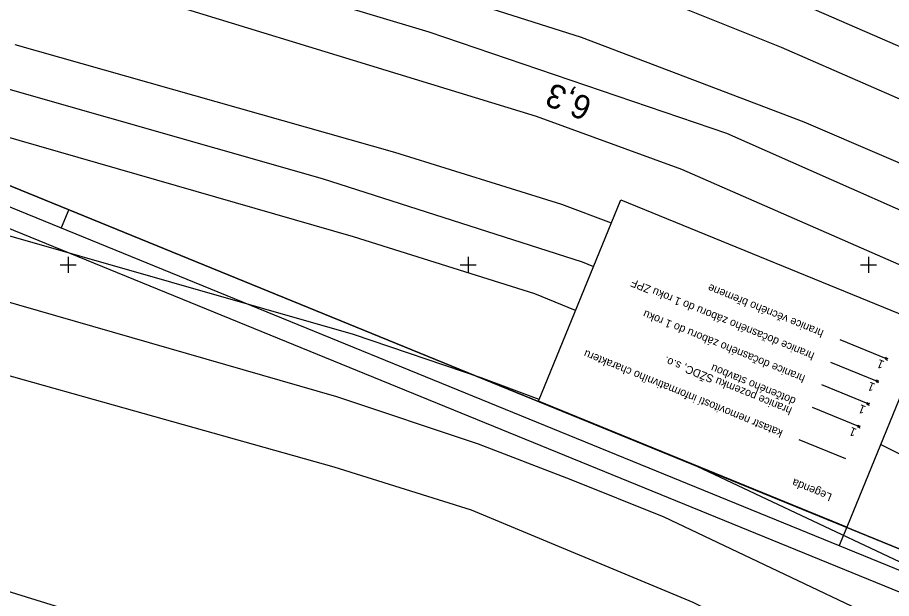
# Model space of a CAD drawing. Extents: x -779302 to -774398, y -1144902 to -1142831.
# Drawn here: x -776612.7 to -776394.2, y -1144283.5 to -1144138.1 of the extents above; entities that cross this region are included whole.
import ezdxf

# ---------------------------------------------------------------- set-up
doc = ezdxf.new("R2010")
doc.units = 0
for name, color, linetype in [('hektosit - Vrstva 5', 7, 'Continuous'), ('Hranice parcel', 7, 'Continuous'), ('legenda - Vrstva 7', 7, 'Continuous'), ('legenda I_5_2 - Vrstva 3', 7, 'Continuous'), ('Vrstva 1', 7, 'Continuous'), ('zjednodus_g_situ-seda - Vrstva 7', 7, 'Continuous')]:
    doc.layers.add(name, color=color, linetype=linetype)

msp = doc.modelspace()

# ---------------------------------------------------------------- linework, layer by layer
at = {"layer": 'hektosit - Vrstva 5'}
for p, q in [((-776600, -1144198), (-776600, -1144202)), ((-776500, -1144198), (-776500, -1144202)), ((-776400, -1144198), (-776400, -1144202)), ((-776602, -1144200), (-776598, -1144200)), ((-776502, -1144200), (-776498, -1144200)), ((-776402, -1144200), (-776398, -1144200))]:
    msp.add_line(p, q, dxfattribs=at)
at = {"layer": 'Hranice parcel'}
for points in [[(-776609.22, -1144072.59), (-776549.62, -1144089.18), (-776477.02, -1144111.9), (-776421.35, -1144132.65), (-776283.48, -1144192.64), (-776246.29, -1144206.67), (-776201.94, -1144223.07), (-776173.05, -1144232.7), (-776113.8, -1144251.1)], [(-776118.46, -1144262.59), (-776213.85, -1144232.45), (-776276.83, -1144209.03), (-776421.73, -1144145.66), (-776463.81, -1144128.69), (-776555.71, -1144099.28), (-776609.79, -1144083.15)], [(-776610.76, -1144099.41), (-776538.78, -1144121.66), (-776471.83, -1144143.05), (-776416.15, -1144164.19), (-776357.31, -1144189.49), (-776292.36, -1144218.98), (-776247.15, -1144237), (-776206.49, -1144251.17), (-776124.24, -1144276.84)], [(-776611.4, -1144111.19), (-776509.83, -1144141.71), (-776435.48, -1144167.03), (-776362.11, -1144199.54), (-776309.74, -1144224.06), (-776263.02, -1144242.23), (-776193.31, -1144267.08), (-776128.39, -1144287.08)], [(-776132.3, -1144298.01), (-776193.18, -1144278.57), (-776239.59, -1144263.48), (-776301.12, -1144240.48), (-776347.51, -1144219.6), (-776446.62, -1144176.16), (-776482.94, -1144162.91), (-776612.01, -1144123.26)], [(-776613.35, -1144144.87), (-776518.43, -1144171.83), (-776476.72, -1144184.79), (-776464.26, -1144189.51)], [(-776616.25, -1144155.62), (-776536.52, -1144178.37), (-776471.51, -1144199.25), (-776468.72, -1144200.44)], [(-776473.19, -1144211.37), (-776483.35, -1144207.28), (-776528.7, -1144193.02), (-776617.26, -1144167.5)], [(-776482.3, -1144233.64), (-776496.78, -1144228.23), (-776528.65, -1144217.4), (-776619.56, -1144191.38)], [(-776145.67, -1144379.15), (-776244.27, -1144349.66), (-776296.05, -1144332.67), (-776327.31, -1144320.71), (-776369.01, -1144302.14), (-776451.08, -1144263.13), (-776474.26, -1144253.76), (-776497.45, -1144244.88), (-776532.83, -1144233.01), (-776621.67, -1144207.38)], [(-776148.27, -1144396.56), (-776184.13, -1144386.14), (-776245.97, -1144366.65), (-776333.82, -1144336.34), (-776380.08, -1144316.22), (-776443.83, -1144284.45), (-776499.21, -1144261.37), (-776533.49, -1144250.6), (-776623.75, -1144225.26)], [(-776139.95, -1144340.89), (-776219.46, -1144316.38), (-776263.77, -1144302.5), (-776324.6, -1144278.51), (-776377.44, -1144254.65), (-776396.98, -1144244.94)], [(-776143.31, -1144363.37), (-776191.33, -1144349.34), (-776249.99, -1144330.39), (-776319.63, -1144305.99), (-776364.66, -1144287.25), (-776444.24, -1144249.74)], [(-776631.25, -1144276.64), (-776433.42, -1144338.06), (-776306.29, -1144376.93), (-776251.08, -1144392.3), (-776152.53, -1144423.14)]]:
    msp.add_lwpolyline(points, dxfattribs=at)
at = {"layer": 'legenda - Vrstva 7'}
msp.add_lwpolyline([(-776405.43, -1144265.6), (-776482.49, -1144234.1), (-776461.9, -1144183.75), (-776384.84, -1144215.25)], close=True, dxfattribs=at)
at = {"layer": 'legenda I_5_2 - Vrstva 3'}
for p, q in [((-776395.45, -1144223.48), (-776407.07, -1144218.74)), ((-776397.76, -1144229.14), (-776409.38, -1144224.39)), ((-776395.19, -1144223.38), (-776395.84, -1144223.65)), ((-776395.71, -1144223.59), (-776395.06, -1144223.32)), ((-776395.34, -1144223.75), (-776395.62, -1144223.09)), ((-776395.56, -1144223.22), (-776395.29, -1144223.88)), ((-776395.45, -1144223.48), (-776395.45, -1144223.48)), ((-776397.65, -1144229.4), (-776397.93, -1144228.74)), ((-776400.07, -1144234.79), (-776411.69, -1144230.04)), ((-776397.5, -1144229.03), (-776398.15, -1144229.3)), ((-776398.02, -1144229.25), (-776397.37, -1144228.97)), ((-776397.87, -1144228.87), (-776397.6, -1144229.53)), ((-776397.76, -1144229.14), (-776397.76, -1144229.14)), ((-776399.81, -1144234.68), (-776400.46, -1144234.95)), ((-776400.33, -1144234.9), (-776399.68, -1144234.62)), ((-776399.96, -1144235.05), (-776400.24, -1144234.4)), ((-776400.18, -1144234.53), (-776399.91, -1144235.18)), ((-776400.07, -1144234.79), (-776400.07, -1144234.79)), ((-776402.38, -1144240.44), (-776414, -1144235.69)), ((-776402.12, -1144240.33), (-776402.77, -1144240.6)), ((-776402.64, -1144240.55), (-776401.99, -1144240.27)), ((-776402.27, -1144240.7), (-776402.55, -1144240.05)), ((-776402.49, -1144240.18), (-776402.22, -1144240.83)), ((-776402.38, -1144240.44), (-776402.38, -1144240.44)), ((-776405.67, -1144248.48), (-776417.28, -1144243.74))]:
    msp.add_line(p, q, dxfattribs=at)
at = {"layer": 'Vrstva 1'}
for p, q in [((-776599.81, -1144186.15), (-776601.7, -1144190.77)), ((-776405.43, -1144265.6), (-776407.32, -1144270.23))]:
    msp.add_line(p, q, dxfattribs=at)
for points in [[(-775713.68, -1144238.31), (-776879.99, -1143761.57), (-776992.36, -1144036.48), (-775826.05, -1144513.22)], [(-775828.78, -1144506.7), (-776985.84, -1144033.74), (-776877.25, -1143768.09), (-775720.2, -1144241.05)], [(-775726.71, -1144243.78), (-776684.76, -1143852.17), (-776789.57, -1144108.58), (-775831.52, -1144500.19)], [(-775831.52, -1144500.19), (-776789.57, -1144108.58), (-776684.76, -1143852.17), (-775726.71, -1144243.78)]]:
    msp.add_lwpolyline(points, close=True, dxfattribs=at)

# ---------------------------------------------------------------- texts
at = {"layer": 'legenda I_5_2 - Vrstva 3'}
for s, height, p in [('hranice dočasného záboru do 1 roku ZPF', 2, (-776413.34, -1144222.06)), ('hranice věcného břemene', 2, (-776411.03, -1144216.4)), ('hranice dočasného záboru do 1 roku', 2, (-776415.65, -1144227.71)), ('katastr nemovitostí informativního charakteru', 2, (-776421.25, -1144241.4)), ('hranice pozemku SŽDC, s.o.', 2, (-776418.94, -1144235.75)), ('1', 2.16, (-776395.85, -1144224.15)), ('dotčeného stavbou', 2, (-776417.96, -1144233.36)), ('1', 2.16, (-776398.16, -1144229.8)), ('1', 2.16, (-776400.47, -1144235.45)), ('1', 2.16, (-776402.78, -1144241.11)), ('Legenda', 2, (-776408.96, -1144257.36))]:
    msp.add_text(s, height=height, rotation=157.7681, dxfattribs=at).set_placement(p)
at = {"layer": 'zjednodus_g_situ-seda - Vrstva 7'}
msp.add_text('6,3', height=6, rotation=157.6995, dxfattribs=at).set_placement((-776468.66, -1144158.55))

doc.saveas('drawing.dxf')
